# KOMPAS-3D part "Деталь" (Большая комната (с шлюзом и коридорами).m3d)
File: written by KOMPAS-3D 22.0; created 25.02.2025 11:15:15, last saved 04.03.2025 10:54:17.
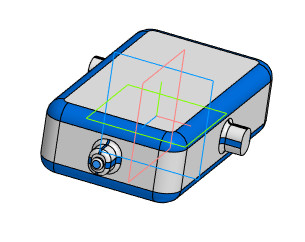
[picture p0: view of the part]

Document properties: Автор: Пользователь Windows; Полное имя файла: C:\Users\Student\Documents\Картошечка\База Сабнатика\Большая комната\Большая комната (с шлюзом и коридорами).m3d

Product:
- Part/product: Деталь
    Масса: 2.257404

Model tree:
1. Эскиз:1
2. Элемент выдавливания:1
     Расстояние 1 = 35
3. Скругление:2  (with: Элемент выдавливания:1)
     Радиус = 10
4. Скругление:1  (with: Элемент выдавливания:1)
     Радиус = 7
5. Эскиз:2  (with: Элемент выдавливания:1)
6. Элемент выдавливания:2
     Расстояние 1 = 10
7. Скругление:3  (with: Элемент выдавливания:2)
     Радиус = 2
8. Эскиз:3  (with: Элемент выдавливания:2)
9. Элемент выдавливания:3
     Расстояние 1 = 2
10. Скругление:4  (with: Элемент выдавливания:3)
     Радиус = 1
11. Скругление:5  (with: Элемент выдавливания:2)
     Радиус = 2
12. Эскиз:4  (with: Элемент выдавливания:1)
13. Элемент выдавливания:4
     Расстояние 1 = 10
14. Скругление:6  (with: Элемент выдавливания:4)
     Радиус = 2
15. Эскиз:5  (with: Элемент выдавливания:1)
16. Элемент выдавливания:5
     Расстояние 1 = 10
17. Скругление:7  (with: Элемент выдавливания:5)
     Радиус = 2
